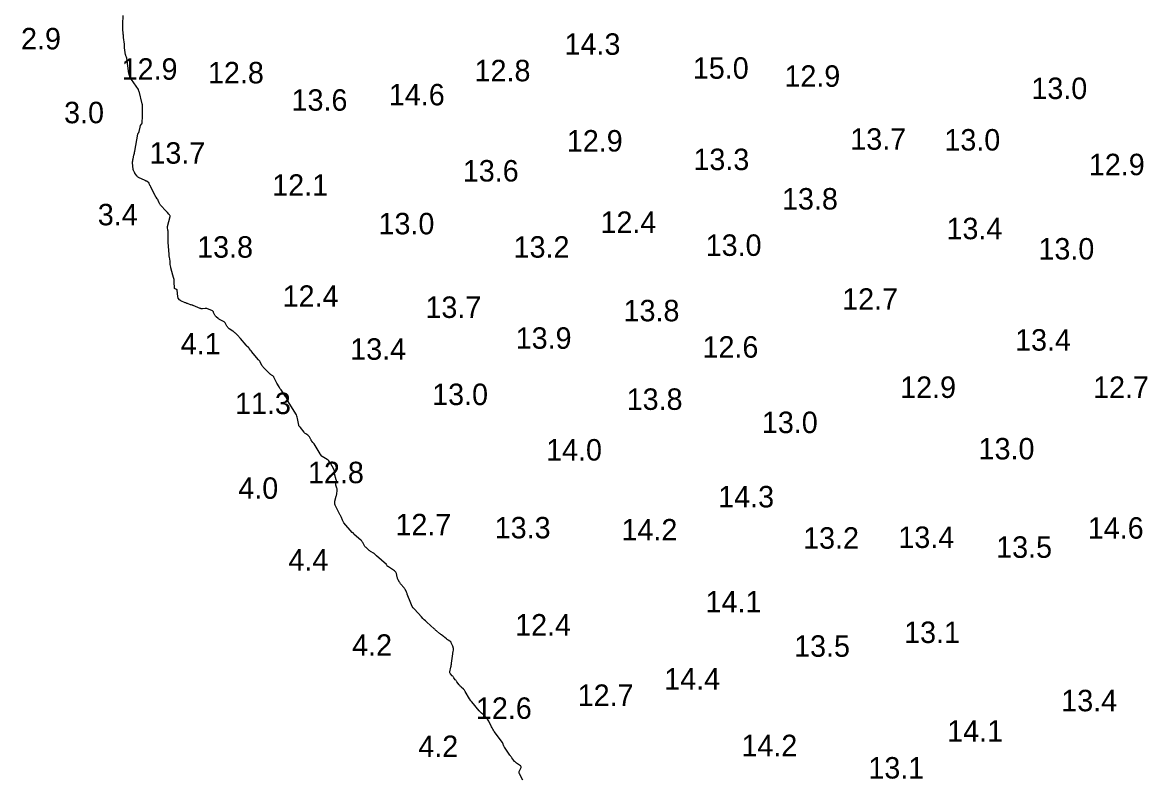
# Model space of a CAD drawing. Extents: x 815352 to 820877, y 582403 to 597439.
# Drawn here: x 816705.1 to 816967.2, y 596960.3 to 597136.7 of the extents above; entities that cross this region are included whole.
import ezdxf

# ---------------------------------------------------------------- set-up
doc = ezdxf.new("R2010")
doc.units = 0
doc.layers.add('V-CONT-EL12', color=7, linetype='Continuous')
doc.layers.add('V-TOPO-SOUN', color=7, linetype='Continuous')

msp = doc.modelspace()

# ---------------------------------------------------------------- linework, layer by layer
at = {"layer": 'V-CONT-EL12'}
msp.add_lwpolyline([(816821.65, 596960.17), (816820.84, 596961.66), (816820.78, 596961.83), (816820.76, 596961.99), (816820.78, 596962.15), (816820.84, 596962.31), (816821.19, 596962.96), (816821.25, 596963.12), (816821.25, 596963.26), (816821.19, 596963.39), (816821.06, 596963.5), (816820.12, 596964.16), (816819.97, 596964.28), (816819.82, 596964.41), (816819.69, 596964.55), (816819.57, 596964.71), (816819.1, 596965.34), (816818.98, 596965.49), (816818.86, 596965.65), (816818.75, 596965.81), (816818.64, 596965.98), (816817.33, 596967.88), (816817.27, 596967.96), (816817.23, 596968.05), (816817.19, 596968.14), (816817.15, 596968.23), (816817.03, 596968.61), (816817, 596968.7), (816816.96, 596968.79), (816816.91, 596968.87), (816816.86, 596968.96), (816814.98, 596971.52), (816814.8, 596971.79), (816814.62, 596972.06), (816814.46, 596972.35), (816814.31, 596972.63), (816813.68, 596973.94), (816813.56, 596974.15), (816813.42, 596974.36), (816813.27, 596974.55), (816813.1, 596974.73), (816812.15, 596975.67), (816812.09, 596975.72), (816812.03, 596975.78), (816811.97, 596975.84), (816811.91, 596975.89), (816811.67, 596976.12), (816811.62, 596976.18), (816811.56, 596976.24), (816811.5, 596976.3), (816811.45, 596976.36), (816809.71, 596978.43), (816809.66, 596978.49), (816809.61, 596978.54), (816809.57, 596978.6), (816809.52, 596978.66), (816809.33, 596978.89), (816809.29, 596978.95), (816809.25, 596979.01), (816809.21, 596979.08), (816809.17, 596979.14), (816808.23, 596980.81), (816808.14, 596980.95), (816808.04, 596981.1), (816807.93, 596981.23), (816807.8, 596981.36), (816807.3, 596981.85), (816807.17, 596981.97), (816807.05, 596982.1), (816806.94, 596982.23), (816806.82, 596982.37), (816806.25, 596983.1), (816806.16, 596983.21), (816806.07, 596983.33), (816805.99, 596983.45), (816805.9, 596983.56), (816805.57, 596984.04), (816805.48, 596984.16), (816805.39, 596984.27), (816805.29, 596984.38), (816805.19, 596984.49), (816804.76, 596984.91), (816804.67, 596985.03), (816804.62, 596985.15), (816804.6, 596985.28), (816804.61, 596985.42), (816804.85, 596986.52), (816804.9, 596986.75), (816804.94, 596986.98), (816804.98, 596987.22), (816805.01, 596987.45), (816805.3, 596989.62), (816805.32, 596989.73), (816805.33, 596989.83), (816805.35, 596989.94), (816805.37, 596990.04), (816805.45, 596990.5), (816805.46, 596990.58), (816805.46, 596990.66), (816805.46, 596990.74), (816805.45, 596990.82), (816805.39, 596991.12), (816805.38, 596991.2), (816805.36, 596991.28), (816805.33, 596991.35), (816805.3, 596991.42), (816804.97, 596992.19), (816804.92, 596992.29), (816804.85, 596992.39), (816804.76, 596992.47), (816804.66, 596992.53), (816804.24, 596992.78), (816804.14, 596992.85), (816804.04, 596992.92), (816803.95, 596992.99), (816803.86, 596993.07), (816803.48, 596993.42), (816803.38, 596993.5), (816803.28, 596993.58), (816803.18, 596993.66), (816803.08, 596993.73), (816802.66, 596994.04), (816802.55, 596994.11), (816802.45, 596994.19), (816802.35, 596994.27), (816802.25, 596994.35), (816801.54, 596994.95), (816801.39, 596995.07), (816801.24, 596995.2), (816801.1, 596995.33), (816800.95, 596995.46), (816799.3, 596996.96), (816798.98, 596997.26), (816798.66, 596997.56), (816798.36, 596997.87), (816798.06, 596998.19), (816796.38, 597000.01), (816796.11, 597000.33), (816795.87, 597000.67), (816795.67, 597001.04), (816795.5, 597001.42), (816794.72, 597003.53), (816794.67, 597003.67), (816794.61, 597003.8), (816794.55, 597003.94), (816794.49, 597004.07), (816794.23, 597004.6), (816794.16, 597004.73), (816794.09, 597004.85), (816794, 597004.97), (816793.91, 597005.08), (816793.24, 597005.83), (816793.14, 597005.95), (816793.05, 597006.08), (816792.96, 597006.2), (816792.88, 597006.34), (816792.58, 597006.88), (816792.51, 597007.02), (816792.45, 597007.16), (816792.4, 597007.31), (816792.36, 597007.46), (816792.17, 597008.32), (816792.11, 597008.5), (816792.02, 597008.66), (816791.9, 597008.8), (816791.75, 597008.93), (816790.36, 597009.87), (816790.32, 597009.89), (816790.29, 597009.91), (816790.26, 597009.93), (816790.22, 597009.95), (816790.09, 597010.03), (816790.06, 597010.05), (816790.03, 597010.07), (816790, 597010.1), (816789.99, 597010.14), (816789.92, 597010.28), (816789.9, 597010.32), (816789.88, 597010.35), (816789.86, 597010.38), (816789.83, 597010.41), (816787.55, 597012.45), (816787.49, 597012.5), (816787.43, 597012.55), (816787.38, 597012.61), (816787.32, 597012.66), (816787.1, 597012.89), (816787.04, 597012.94), (816786.99, 597012.99), (816786.92, 597013.03), (816786.86, 597013.07), (816786.29, 597013.39), (816786.17, 597013.46), (816786.06, 597013.54), (816785.96, 597013.62), (816785.85, 597013.7), (816785.1, 597014.37), (816784.97, 597014.49), (816784.85, 597014.63), (816784.75, 597014.77), (816784.66, 597014.92), (816784.32, 597015.56), (816784.23, 597015.72), (816784.13, 597015.86), (816784.01, 597015.99), (816783.87, 597016.12), (816782.36, 597017.38), (816782.33, 597017.4), (816782.3, 597017.44), (816782.28, 597017.47), (816782.26, 597017.51), (816782.2, 597017.69), (816782.18, 597017.72), (816782.16, 597017.75), (816782.13, 597017.77), (816782.1, 597017.79), (816781.96, 597017.84), (816781.93, 597017.85), (816781.9, 597017.87), (816781.87, 597017.9), (816781.84, 597017.92), (816779.96, 597020.16), (816779.86, 597020.3), (816779.77, 597020.44), (816779.69, 597020.58), (816779.62, 597020.73), (816779.36, 597021.35), (816779.29, 597021.5), (816779.22, 597021.66), (816779.15, 597021.81), (816779.08, 597021.96), (816777.94, 597024.28), (816777.85, 597024.51), (816777.81, 597024.74), (816777.81, 597024.98), (816777.86, 597025.21), (816778.18, 597026.36), (816778.22, 597026.51), (816778.25, 597026.66), (816778.28, 597026.82), (816778.3, 597026.97), (816778.36, 597027.6), (816778.37, 597027.75), (816778.36, 597027.9), (816778.34, 597028.06), (816778.3, 597028.21), (816778.07, 597028.93), (816778.05, 597029.03), (816778.04, 597029.12), (816778.04, 597029.22), (816778.06, 597029.32), (816778.17, 597029.72), (816778.2, 597029.82), (816778.2, 597029.92), (816778.19, 597030.02), (816778.17, 597030.12), (816777.76, 597031.56), (816777.74, 597031.63), (816777.72, 597031.71), (816777.72, 597031.78), (816777.72, 597031.86), (816777.73, 597032.17), (816777.73, 597032.24), (816777.72, 597032.32), (816777.7, 597032.39), (816777.67, 597032.46), (816776.76, 597034.16), (816776.62, 597034.37), (816776.47, 597034.55), (816776.29, 597034.72), (816776.08, 597034.86), (816774.88, 597035.56), (816774.83, 597035.59), (816774.78, 597035.64), (816774.74, 597035.68), (816774.7, 597035.74), (816774.55, 597035.96), (816774.52, 597036.01), (816774.48, 597036.07), (816774.45, 597036.12), (816774.41, 597036.18), (816772.98, 597038.52), (816772.92, 597038.61), (816772.86, 597038.7), (816772.8, 597038.78), (816772.74, 597038.86), (816772.48, 597039.19), (816772.41, 597039.28), (816772.35, 597039.36), (816772.3, 597039.45), (816772.25, 597039.54), (816771.9, 597040.15), (816771.83, 597040.27), (816771.74, 597040.37), (816771.64, 597040.47), (816771.53, 597040.55), (816771.06, 597040.85), (816770.95, 597040.93), (816770.85, 597041.02), (816770.75, 597041.12), (816770.67, 597041.23), (816769.87, 597042.33), (816769.83, 597042.38), (816769.79, 597042.43), (816769.75, 597042.48), (816769.7, 597042.52), (816769.52, 597042.7), (816769.48, 597042.75), (816769.44, 597042.8), (816769.42, 597042.86), (816769.41, 597042.92), (816769.15, 597044.48), (816769.09, 597044.76), (816769.01, 597045.03), (816768.9, 597045.29), (816768.76, 597045.54), (816766.98, 597048.41), (816766.95, 597048.46), (816766.93, 597048.51), (816766.91, 597048.56), (816766.89, 597048.61), (816766.83, 597048.81), (816766.81, 597048.87), (816766.79, 597048.91), (816766.77, 597048.96), (816766.74, 597049.01), (816766.54, 597049.3), (816766.49, 597049.36), (816766.45, 597049.42), (816766.41, 597049.49), (816766.36, 597049.55), (816765.3, 597051.1), (816765.17, 597051.28), (816765.05, 597051.46), (816764.94, 597051.65), (816764.83, 597051.83), (816764.34, 597052.65), (816764.25, 597052.81), (816764.17, 597052.96), (816764.09, 597053.13), (816764.01, 597053.29), (816763.65, 597054.1), (816763.6, 597054.18), (816763.54, 597054.25), (816763.48, 597054.32), (816763.4, 597054.37), (816763.05, 597054.56), (816762.97, 597054.61), (816762.89, 597054.67), (816762.82, 597054.73), (816762.74, 597054.79), (816761.43, 597056.09), (816761.29, 597056.24), (816761.16, 597056.39), (816761.04, 597056.56), (816760.94, 597056.73), (816760.54, 597057.45), (816760.44, 597057.62), (816760.33, 597057.79), (816760.21, 597057.96), (816760.08, 597058.12), (816758.44, 597060.03), (816758.38, 597060.11), (816758.31, 597060.19), (816758.25, 597060.27), (816758.19, 597060.35), (816757.96, 597060.68), (816757.9, 597060.75), (816757.84, 597060.83), (816757.77, 597060.9), (816757.7, 597060.97), (816757.42, 597061.25), (816757.35, 597061.32), (816757.29, 597061.39), (816757.22, 597061.46), (816757.16, 597061.54), (816755.85, 597063.11), (816755.71, 597063.27), (816755.58, 597063.42), (816755.44, 597063.57), (816755.29, 597063.72), (816754.72, 597064.31), (816754.57, 597064.45), (816754.41, 597064.59), (816754.25, 597064.72), (816754.08, 597064.83), (816753.25, 597065.38), (816753.09, 597065.5), (816752.94, 597065.63), (816752.81, 597065.79), (816752.7, 597065.96), (816752.25, 597066.73), (816752.16, 597066.87), (816752.05, 597066.98), (816751.92, 597067.08), (816751.77, 597067.15), (816751.1, 597067.44), (816750.98, 597067.5), (816750.85, 597067.57), (816750.74, 597067.65), (816750.63, 597067.74), (816750.2, 597068.12), (816750.09, 597068.22), (816750.01, 597068.33), (816749.93, 597068.44), (816749.87, 597068.57), (816749.6, 597069.18), (816749.53, 597069.32), (816749.43, 597069.43), (816749.31, 597069.52), (816749.18, 597069.59), (816748.16, 597070), (816748.02, 597070.05), (816747.88, 597070.08), (816747.74, 597070.09), (816747.59, 597070.08), (816747, 597070.03), (816746.86, 597070.02), (816746.72, 597070.04), (816746.58, 597070.07), (816746.44, 597070.11), (816744.79, 597070.8), (816744.74, 597070.82), (816744.69, 597070.83), (816744.64, 597070.85), (816744.59, 597070.86), (816744.38, 597070.91), (816744.33, 597070.93), (816744.28, 597070.94), (816744.23, 597070.96), (816744.18, 597070.98), (816743.5, 597071.23), (816743.37, 597071.28), (816743.24, 597071.33), (816743.11, 597071.38), (816742.99, 597071.43), (816741.96, 597071.88), (816741.87, 597071.93), (816741.78, 597071.99), (816741.7, 597072.06), (816741.63, 597072.14), (816741.37, 597072.5), (816741.32, 597072.59), (816741.27, 597072.69), (816741.24, 597072.79), (816741.23, 597072.9), (816741.12, 597074.33), (816741.1, 597074.41), (816741.07, 597074.47), (816741.02, 597074.51), (816740.95, 597074.54), (816740.64, 597074.64), (816740.57, 597074.67), (816740.52, 597074.72), (816740.49, 597074.78), (816740.48, 597074.85), (816740.44, 597076.29), (816740.42, 597076.55), (816740.39, 597076.81), (816740.34, 597077.07), (816740.27, 597077.33), (816739.72, 597079.26), (816739.69, 597079.38), (816739.66, 597079.49), (816739.63, 597079.61), (816739.61, 597079.72), (816739.5, 597080.32), (816739.49, 597080.37), (816739.48, 597080.42), (816739.48, 597080.47), (816739.47, 597080.52), (816739.46, 597080.76), (816739.45, 597080.79), (816739.45, 597080.82), (816739.46, 597080.85), (816739.46, 597080.89), (816739.47, 597081.01), (816739.47, 597081.05), (816739.47, 597081.08), (816739.47, 597081.11), (816739.46, 597081.14), (816739.3, 597082.05), (816739.27, 597082.22), (816739.24, 597082.38), (816739.23, 597082.55), (816739.21, 597082.71), (816738.98, 597085.58), (816738.98, 597085.6), (816738.98, 597085.63), (816738.98, 597085.65), (816738.98, 597085.68), (816738.97, 597085.78), (816738.97, 597085.8), (816738.97, 597085.83), (816738.97, 597085.85), (816738.97, 597085.88), (816738.97, 597088.19), (816738.96, 597088.27), (816738.96, 597088.35), (816738.95, 597088.43), (816738.93, 597088.51), (816738.86, 597088.83), (816738.85, 597088.91), (816738.85, 597088.99), (816738.85, 597089.07), (816738.87, 597089.16), (816739.45, 597091.55), (816739.46, 597091.6), (816739.46, 597091.65), (816739.44, 597091.7), (816739.42, 597091.75), (816739.29, 597091.94), (816739.25, 597091.98), (816739.22, 597092.03), (816739.18, 597092.07), (816739.15, 597092.11), (816738.81, 597092.49), (816738.74, 597092.56), (816738.67, 597092.64), (816738.6, 597092.72), (816738.53, 597092.79), (816737.25, 597094.2), (816737.16, 597094.31), (816737.07, 597094.43), (816737, 597094.55), (816736.94, 597094.68), (816736.68, 597095.26), (816736.64, 597095.36), (816736.58, 597095.46), (816736.53, 597095.55), (816736.47, 597095.65), (816736.21, 597096.01), (816736.15, 597096.1), (816736.09, 597096.2), (816736.03, 597096.29), (816735.98, 597096.39), (816735, 597098.4), (816734.96, 597098.48), (816734.92, 597098.56), (816734.88, 597098.64), (816734.83, 597098.71), (816734.6, 597099.13), (816734.59, 597099.15), (816734.59, 597099.18), (816734.58, 597099.2), (816734.58, 597099.22), (816734.57, 597099.31), (816734.57, 597099.34), (816734.56, 597099.36), (816734.55, 597099.37), (816734.54, 597099.39), (816734.45, 597099.47), (816734.42, 597099.49), (816734.4, 597099.5), (816734.38, 597099.52), (816734.35, 597099.53), (816733.97, 597099.73), (816733.9, 597099.77), (816733.83, 597099.81), (816733.75, 597099.84), (816733.68, 597099.88), (816732.13, 597100.64), (816732, 597100.71), (816731.89, 597100.8), (816731.78, 597100.91), (816731.69, 597101.03), (816731.27, 597101.65), (816731.22, 597101.72), (816731.18, 597101.79), (816731.13, 597101.87), (816731.09, 597101.94), (816730.92, 597102.24), (816730.89, 597102.32), (816730.86, 597102.4), (816730.84, 597102.48), (816730.83, 597102.57), (816730.73, 597104.04), (816730.73, 597104.27), (816730.74, 597104.5), (816730.77, 597104.72), (816730.82, 597104.95), (816731.04, 597105.84), (816731.09, 597106.06), (816731.14, 597106.28), (816731.19, 597106.51), (816731.23, 597106.74), (816731.95, 597110.71), (816731.96, 597110.76), (816731.98, 597110.82), (816732, 597110.87), (816732.03, 597110.91), (816732.16, 597111.1), (816732.19, 597111.15), (816732.21, 597111.2), (816732.23, 597111.26), (816732.24, 597111.31), (816732.45, 597112.36), (816732.47, 597112.45), (816732.5, 597112.54), (816732.54, 597112.63), (816732.59, 597112.71), (816732.81, 597113.04), (816732.86, 597113.13), (816732.89, 597113.22), (816732.92, 597113.31), (816732.93, 597113.41), (816733.03, 597114.84), (816733.03, 597114.87), (816733.03, 597114.9), (816733.03, 597114.92), (816733.02, 597114.95), (816733.01, 597115.06), (816733.01, 597115.08), (816733, 597115.11), (816733, 597115.14), (816733, 597115.16), (816733, 597115.29), (816733, 597115.32), (816733, 597115.35), (816733, 597115.38), (816733, 597115.41), (816733.05, 597116.84), (816733.05, 597117.08), (816733.03, 597117.33), (816733, 597117.57), (816732.95, 597117.81), (816732.21, 597120.7), (816732.2, 597120.73), (816732.19, 597120.77), (816732.18, 597120.8), (816732.17, 597120.84), (816732.13, 597120.98), (816732.12, 597121.02), (816732.11, 597121.05), (816732.09, 597121.08), (816732.07, 597121.11), (816730.46, 597123.48), (816730.45, 597123.5), (816730.43, 597123.51), (816730.42, 597123.53), (816730.4, 597123.55), (816730.34, 597123.61), (816730.32, 597123.63), (816730.31, 597123.64), (816730.29, 597123.66), (816730.27, 597123.67), (816730.18, 597123.73), (816730.17, 597123.74), (816730.15, 597123.76), (816730.14, 597123.78), (816730.13, 597123.8), (816729.96, 597124.42), (816729.94, 597124.54), (816729.91, 597124.65), (816729.89, 597124.76), (816729.87, 597124.87), (816729.35, 597128.43), (816729.34, 597128.5), (816729.32, 597128.56), (816729.3, 597128.63), (816729.28, 597128.69), (816729.17, 597128.95), (816729.15, 597129.02), (816729.13, 597129.08), (816729.11, 597129.15), (816729.1, 597129.22), (816728.86, 597130.81), (816728.85, 597130.89), (816728.84, 597130.96), (816728.84, 597131.04), (816728.83, 597131.11), (816728.83, 597131.41), (816728.83, 597131.49), (816728.83, 597131.56), (816728.82, 597131.64), (816728.81, 597131.71), (816728.61, 597133.26), (816728.6, 597133.32), (816728.6, 597133.38), (816728.59, 597133.45), (816728.59, 597133.51), (816728.57, 597133.75), (816728.56, 597133.81), (816728.56, 597133.88), (816728.55, 597133.94), (816728.55, 597134), (816728.47, 597135.37), (816728.46, 597135.62), (816728.45, 597135.87), (816728.45, 597136.12), (816728.46, 597136.37), (816728.54, 597138.4)], dxfattribs=at)

# ---------------------------------------------------------------- texts
at = {"layer": 'V-TOPO-SOUN'}
for s, p in [('2.9', (816704.73, 597130.48)), ('14.3 ', (816831.35, 597129.21)), ('12.9 ', (816728.17, 597123.4)), ('12.8 ', (816748.28, 597122.55)), ('12.8 ', (816810.39, 597123.04)), ('15.0 ', (816861.24, 597123.63)), ('12.9 ', (816882.57, 597121.76)), ('13.0 ', (816940.11, 597118.9)), ('13.6 ', (816767.75, 597116.18)), ('14.6 ', (816790.42, 597117.43)), ('3.0', (816714.76, 597113.26)), ('12.9 ', (816831.88, 597106.67)), ('13.7 ', (816897.92, 597107.09)), ('13.0 ', (816919.84, 597106.9)), ('13.7 ', (816734.64, 597103.84)), ('13.3 ', (816861.37, 597102.34)), ('12.9 ', (816953.5, 597101.15)), ('13.6 ', (816807.65, 597099.68)), ('12.1 ', (816763.25, 597096.36)), ('13.8 ', (816882.01, 597093.15)), ('3.4', (816722.61, 597089.47)), ('13.0 ', (816788.01, 597087.37)), ('12.4 ', (816839.72, 597087.7)), ('13.4 ', (816920.33, 597086.23)), ('13.0 ', (816864.23, 597082.35)), ('13.8 ', (816745.76, 597081.93)), ('13.2 ', (816819.48, 597081.93)), ('13.0 ', (816941.75, 597081.5)), ('12.4 ', (816765.67, 597070.48)), ('12.7 ', (816896.02, 597069.79)), ('13.7 ', (816798.94, 597067.89)), ('13.8 ', (816845.1, 597067.1)), ('4.1', (816741.94, 597059.39)), ('13.9 ', (816819.97, 597060.7)), ('12.6 ', (816863.49, 597058.63)), ('13.4 ', (816936.31, 597060.27)), ('13.4 ', (816781.42, 597058.14)), ('12.9 ', (816909.54, 597049.25)), ('12.7 ', (816954.48, 597049.25)), ('11.3 ', (816754.58, 597045.48)), ('13.0 ', (816800.51, 597047.58)), ('13.8 ', (816845.82, 597046.46)), ('13.0 ', (816877.32, 597041.05)), ('13.0 ', (816927.81, 597034.91)), ('14.0 ', (816827.05, 597034.65)), ('12.8 ', (816771.58, 597029.37)), ('4.0', (816755.35, 597025.73)), ('14.3 ', (816867.15, 597023.73)), ('12.7 ', (816791.95, 597017.23)), ('13.3 ', (816815.08, 597016.51)), ('14.2 ', (816844.61, 597016.02)), ('13.2 ', (816886.93, 597014.11)), ('13.4 ', (816909.11, 597014.28)), ('14.6 ', (816953.25, 597016.44)), ('13.5 ', (816931.91, 597011.98)), ('4.4', (816767.03, 597009)), ('14.1 ', (816864.2, 596999.25)), ('12.4 ', (816819.84, 596993.87)), ('13.1 ', (816910.46, 596992.13)), ('4.2', (816781.86, 596989.15)), ('13.5 ', (816884.83, 596988.92)), ('14.4 ', (816854.58, 596981.27)), ('12.7 ', (816834.41, 596977.47)), ('13.4 ', (816947.07, 596976.22)), ('12.6 ', (816810.7, 596974.45)), ('14.1 ', (816920.5, 596969.13)), ('4.2', (816797.28, 596965.56)), ('14.2 ', (816872.56, 596965.75)), ('13.1 ', (816902.13, 596960.54))]:
    msp.add_text(s, height=5, dxfattribs=at).set_placement(p)

doc.saveas('drawing.dxf')
